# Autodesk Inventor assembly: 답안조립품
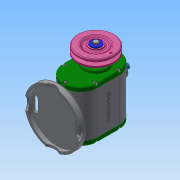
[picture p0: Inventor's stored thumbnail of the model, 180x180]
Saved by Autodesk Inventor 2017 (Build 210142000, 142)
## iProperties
Part Number: 답안조립품
Material: 일반
Document SubType Name: Assembly
Designer: user
Author: user
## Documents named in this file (19)
- C:\Users\user\Desktop\611006V1008\답안조립품.iam
- C:\Users\user\Desktop\611006V1008\V-벨트풀리.ipt
- C:\Users\user\Desktop\611006V1008\가변스프링.ipt
- C:\Users\user\Desktop\611006V1008\뒤커버.ipt
- C:\Users\user\Desktop\611006V1008\멈춤나사 M3.ipt
- C:\Users\user\Desktop\611006V1008\메인축.ipt
- C:\Users\user\Desktop\611006V1008\베어링 608.ipt
- C:\Users\user\Desktop\611006V1008\베어링 6003.ipt
- C:\Users\user\Desktop\611006V1008\본체.ipt
- C:\Users\user\Desktop\611006V1008\볼트 M4.ipt
- C:\Users\user\Desktop\611006V1008\볼트 M6.ipt
- C:\Users\user\Desktop\611006V1008\부시.ipt
- C:\Users\user\Desktop\611006V1008\서브축.ipt
- C:\Users\user\Desktop\611006V1008\슬라이더.ipt
- C:\Users\user\Desktop\611006V1008\앞커버.ipt
- C:\Users\user\Desktop\611006V1008\오일실 8x22x7.ipt
- C:\Users\user\Desktop\611006V1008\오일실 17x32x8.ipt
- C:\Users\user\Desktop\611006V1008\와셔.ipt
- C:\Users\user\Desktop\611006V1008\키 5x5.ipt
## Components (2 placed, 2 different names)
1. V-벨트풀리:1 — 플러쉬:1, 각도:2
2. 가변스프링:1
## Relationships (2: Flush 1, Angle 1)
- 플러쉬:1 [Flush]: V-벨트풀리:1
- 각도:2 [Angle]: V-벨트풀리:1
